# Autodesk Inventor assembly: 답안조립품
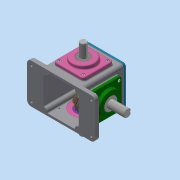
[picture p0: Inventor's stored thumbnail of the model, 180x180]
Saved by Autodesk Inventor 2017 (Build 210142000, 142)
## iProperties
Part Number: 답안조립품
Material: 일반
Document SubType Name: Assembly
Designer: MRC
Author: MRC
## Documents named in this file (16)
- C:\Users\MRC\Desktop\620307V1009\답안조립품.iam
- C:\Users\MRC\Desktop\620307V1009\본체.ipt
- C:\Users\MRC\Desktop\620307V1009\개스킷.ipt
- C:\Users\MRC\Desktop\620307V1009\메인베벨기어.ipt
- C:\Users\MRC\Desktop\620307V1009\메인축.ipt
- C:\Users\MRC\Desktop\620307V1009\메인커버.ipt
- C:\Users\MRC\Desktop\620307V1009\베어링 6203.ipt
- C:\Users\MRC\Desktop\620307V1009\베어링 6204.ipt
- C:\Users\MRC\Desktop\620307V1009\볼트 M4.ipt
- C:\Users\MRC\Desktop\620307V1009\상부커버.ipt
- C:\Users\MRC\Desktop\620307V1009\서브베벨기어.ipt
- C:\Users\MRC\Desktop\620307V1009\서브축.ipt
- C:\Users\MRC\Desktop\620307V1009\서브커버.ipt
- C:\Users\MRC\Desktop\620307V1009\오일 실 17 32 8.ipt
- C:\Users\MRC\Desktop\620307V1009\오일 실 20 35 8.ipt
- C:\Users\MRC\Desktop\620307V1009\키 4x4.ipt
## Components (1 placed, 1 different names)
1. 개스킷:1
